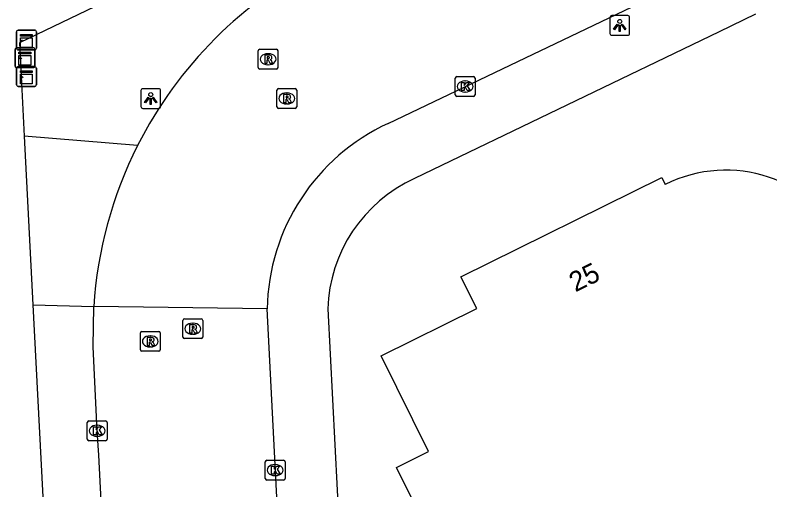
# Model space of a CAD drawing. Extents: x 157692 to 159670, y 381454 to 383289.
# Drawn here: x 158005 to 158043.16, y 381618.5 to 381642.51 of the extents above; entities that cross this region are included whole.
import ezdxf

# ---------------------------------------------------------------- set-up
doc = ezdxf.new("R2010")
doc.units = 0
for name, color, linetype in [('IMGEO_Kast', 7, 'Continuous'), ('IMGEO_Kolk', 7, 'Continuous'), ('IMGEO_Lichtpunt', 7, 'Continuous'), ('IMGEO_Pand', 7, 'Continuous'), ('IMGEO_Pand_nummerreeks', 7, 'Continuous'), ('IMGEO_Rijbaan_lokaal_gesloten', 7, 'Continuous'), ('IMGEO_Rioolput', 7, 'Continuous'), ('IMGEO_Voetpad_open', 7, 'Continuous')]:
    doc.layers.add(name, color=color, linetype=linetype)

msp = doc.modelspace()

# ---------------------------------------------------------------- linework, layer by layer
at = {"layer": 'IMGEO_Kast'}
for p, q in [((158005.076, 381640.825), (158005.076, 381641.666)), ((158005.076, 381641.666), (158005.076, 381640.825)), ((158005.151, 381641.75), (158005.992, 381641.75)), ((158005.992, 381641.75), (158005.151, 381641.75)), ((158006.076, 381641.675), (158006.076, 381640.834)), ((158006.076, 381640.834), (158006.076, 381641.675)), ((158005.001, 381639.931), (158005.001, 381640.772)), ((158005.001, 381640.772), (158005.001, 381639.931)), ((158005.076, 381640.856), (158005.917, 381640.856)), ((158005.917, 381640.856), (158005.076, 381640.856)), ((158006.001, 381640.75), (158005.16, 381640.75)), ((158005.16, 381640.75), (158006.001, 381640.75)), ((158006.001, 381640.781), (158006.001, 381639.94)), ((158006.001, 381639.94), (158006.001, 381640.781)), ((158005.075, 381638.983), (158005.075, 381639.824)), ((158005.075, 381639.824), (158005.075, 381638.983)), ((158005.926, 381639.856), (158005.085, 381639.856)), ((158005.085, 381639.856), (158005.926, 381639.856)), ((158005.15, 381639.908), (158005.991, 381639.908)), ((158005.991, 381639.908), (158005.15, 381639.908)), ((158006.075, 381639.833), (158006.075, 381638.992)), ((158006.075, 381638.992), (158006.075, 381639.833)), ((158006, 381638.908), (158005.159, 381638.908)), ((158005.159, 381638.908), (158006, 381638.908))]:
    msp.add_line(p, q, dxfattribs=at)
for points in [[(158005.271, 381641.54), (158005.871, 381641.54), (158005.871, 381641.455), (158005.271, 381641.455), (158005.271, 381641.54)], [(158005.271, 381641.365), (158005.871, 381641.365), (158005.871, 381640.876), (158005.271, 381640.876), (158005.271, 381641.365)], [(158005.196, 381640.646), (158005.796, 381640.646), (158005.796, 381640.561), (158005.196, 381640.561), (158005.196, 381640.646)], [(158005.196, 381640.471), (158005.796, 381640.471), (158005.796, 381639.982), (158005.196, 381639.982), (158005.196, 381640.471)], [(158005.27, 381639.698), (158005.87, 381639.698), (158005.87, 381639.613), (158005.27, 381639.613), (158005.27, 381639.698)], [(158005.27, 381639.523), (158005.87, 381639.523), (158005.87, 381639.034), (158005.27, 381639.034), (158005.27, 381639.523)]]:
    msp.add_lwpolyline(points, dxfattribs=at)
for centre in [(158005.355, 381641.214), (158005.28, 381640.32), (158005.354, 381639.372)]:
    msp.add_circle(centre, 0.0377, dxfattribs=at)
for centre, start, end in [((158005.154, 381641.672), 92.4484, 184.2845), ((158005.154, 381641.672), 92.4484, 184.2845), ((158005.998, 381641.672), 2.4484, 94.2845), ((158005.998, 381641.672), 2.4484, 94.2845), ((158005.079, 381640.778), 92.4484, 184.2845), ((158005.079, 381640.778), 92.4484, 184.2845), ((158005.154, 381640.828), 182.4484, 274.2845), ((158005.154, 381640.828), 182.4484, 274.2845), ((158005.923, 381640.778), 2.4484, 94.2845), ((158005.923, 381640.778), 2.4484, 94.2845), ((158005.998, 381640.828), 272.4484, 4.2845), ((158005.998, 381640.828), 272.4484, 4.2845), ((158005.079, 381639.934), 182.4484, 274.2845), ((158005.079, 381639.934), 182.4484, 274.2845), ((158005.153, 381639.83), 92.4484, 184.2845), ((158005.153, 381639.83), 92.4484, 184.2845), ((158005.923, 381639.934), 272.4484, 4.2845), ((158005.923, 381639.934), 272.4484, 4.2845), ((158005.997, 381639.83), 2.4484, 94.2845), ((158005.997, 381639.83), 2.4484, 94.2845), ((158005.153, 381638.986), 182.4484, 274.2845), ((158005.153, 381638.986), 182.4484, 274.2845), ((158005.997, 381638.986), 272.4484, 4.2845), ((158005.997, 381638.986), 272.4484, 4.2845)]:
    msp.add_arc(centre, 0.0779, start, end, dxfattribs=at)
at = {"layer": 'IMGEO_Kolk'}
for p, q in [((158027.33, 381639.402), (158028.182, 381639.402)), ((158027.255, 381638.476), (158027.255, 381639.328)), ((158027.743, 381639.182), (158027.768, 381639.182)), ((158028.256, 381639.328), (158028.256, 381638.476)), ((158027.766, 381638.622), (158027.741, 381638.622)), ((158028.182, 381638.402), (158027.33, 381638.402)), ((158008.652, 381621.062), (158008.652, 381621.914)), ((158008.727, 381621.988), (158009.579, 381621.988)), ((158009.653, 381621.914), (158009.653, 381621.062)), ((158009.14, 381621.768), (158009.165, 381621.768)), ((158009.163, 381621.208), (158009.138, 381621.208)), ((158009.579, 381620.988), (158008.727, 381620.988)), ((158017.651, 381619.073), (158017.651, 381619.925)), ((158017.726, 381619.999), (158018.578, 381619.999)), ((158018.652, 381619.925), (158018.652, 381619.073)), ((158018.139, 381619.779), (158018.164, 381619.779)), ((158018.162, 381619.219), (158018.137, 381619.219)), ((158018.578, 381618.999), (158017.726, 381618.999))]:
    msp.add_line(p, q, dxfattribs=at)
for points in [[(158027.33, 381639.402), (158028.182, 381639.402)], [(158027.255, 381638.476), (158027.255, 381639.328)], [(158027.576, 381639.102), (158027.699, 381639.102), (158027.699, 381638.951), (158027.829, 381639.102), (158027.993, 381639.102), (158027.847, 381638.951), (158028, 381638.702), (158027.848, 381638.702), (158027.763, 381638.866), (158027.699, 381638.799), (158027.699, 381638.702), (158027.576, 381638.702), (158027.576, 381639.102)], [(158028.256, 381639.328), (158028.256, 381638.476)], [(158028.182, 381638.402), (158027.33, 381638.402)], [(158008.652, 381621.062), (158008.652, 381621.914)], [(158008.727, 381621.988), (158009.579, 381621.988)], [(158009.653, 381621.914), (158009.653, 381621.062)], [(158008.973, 381621.688), (158009.096, 381621.688), (158009.096, 381621.537), (158009.226, 381621.688), (158009.39, 381621.688), (158009.244, 381621.537), (158009.397, 381621.288), (158009.245, 381621.288), (158009.16, 381621.452), (158009.096, 381621.385), (158009.096, 381621.288), (158008.973, 381621.288), (158008.973, 381621.688)], [(158009.579, 381620.988), (158008.727, 381620.988)], [(158017.651, 381619.073), (158017.651, 381619.925)], [(158017.726, 381619.999), (158018.578, 381619.999)], [(158018.652, 381619.925), (158018.652, 381619.073)], [(158017.972, 381619.699), (158018.095, 381619.699), (158018.095, 381619.548), (158018.225, 381619.699), (158018.389, 381619.699), (158018.243, 381619.548), (158018.396, 381619.299), (158018.244, 381619.299), (158018.159, 381619.463), (158018.095, 381619.396), (158018.095, 381619.299), (158017.972, 381619.299), (158017.972, 381619.699)], [(158018.578, 381618.999), (158017.726, 381618.999)]]:
    msp.add_lwpolyline(points, dxfattribs=at)
for centre, start, end in [((158027.332, 381639.326), 91.552, 178.448), ((158027.332, 381639.326), 91.552, 178.448), ((158028.18, 381639.326), 1.552, 88.448), ((158028.18, 381639.326), 1.552, 88.448), ((158027.332, 381638.478), 181.552, 268.448), ((158027.332, 381638.478), 181.552, 268.448), ((158028.18, 381638.478), 271.552, 358.448), ((158028.18, 381638.478), 271.552, 358.448), ((158008.729, 381621.912), 91.552, 178.448), ((158008.729, 381621.912), 91.552, 178.448), ((158009.577, 381621.912), 1.552, 88.448), ((158009.577, 381621.912), 1.552, 88.448), ((158008.729, 381621.064), 181.552, 268.448), ((158008.729, 381621.064), 181.552, 268.448), ((158009.577, 381621.064), 271.552, 358.448), ((158009.577, 381621.064), 271.552, 358.448), ((158017.728, 381619.923), 91.552, 178.448), ((158017.728, 381619.923), 91.552, 178.448), ((158018.576, 381619.923), 1.552, 88.448), ((158018.576, 381619.923), 1.552, 88.448), ((158017.728, 381619.075), 181.552, 268.448), ((158017.728, 381619.075), 181.552, 268.448), ((158018.576, 381619.075), 271.552, 358.448), ((158018.576, 381619.075), 271.552, 358.448)]:
    msp.add_arc(centre, 0.0765, start, end, dxfattribs=at)
for centre, major_axis, ratio, start_param, end_param in [((158027.742, 381638.902), (-0.387, 0.002), 0.722429, 4.712389, 7.853982), ((158027.767, 381638.902), (-0.39, 0.002), 0.717154, 1.570796, 4.712389), ((158009.139, 381621.488), (-0.387, 0.002), 0.722429, 4.712389, 7.853982), ((158009.164, 381621.488), (-0.39, 0.002), 0.717154, 1.570796, 4.712389), ((158018.138, 381619.499), (-0.387, 0.002), 0.722429, 4.712389, 7.853982), ((158018.163, 381619.499), (-0.39, 0.002), 0.717154, 1.570796, 4.712389)]:
    msp.add_ellipse(centre, major_axis=major_axis, ratio=ratio, start_param=start_param, end_param=end_param, dxfattribs=at)
at = {"layer": 'IMGEO_Lichtpunt'}
for p, q in [((158035.974, 381642.489), (158035.166, 381642.489)), ((158035.974, 381642.489), (158035.166, 381642.489)), ((158035.072, 381642.394), (158035.072, 381641.587)), ((158035.072, 381642.394), (158035.072, 381641.587)), ((158036.068, 381641.587), (158036.068, 381642.394)), ((158036.068, 381641.587), (158036.068, 381642.394)), ((158035.166, 381641.493), (158035.974, 381641.493)), ((158035.166, 381641.493), (158035.974, 381641.493)), ((158011.361, 381638.695), (158011.361, 381637.888)), ((158011.361, 381638.695), (158011.361, 381637.888)), ((158012.263, 381638.79), (158011.455, 381638.79)), ((158012.263, 381638.79), (158011.455, 381638.79)), ((158012.357, 381637.888), (158012.357, 381638.695)), ((158012.357, 381637.888), (158012.357, 381638.695)), ((158011.455, 381637.794), (158012.263, 381637.794)), ((158011.455, 381637.794), (158012.263, 381637.794))]:
    msp.add_line(p, q, dxfattribs=at)
for points in [[(158035.446, 381642.058), (158035.485, 381642.03), (158035.297, 381641.768), (158035.259, 381641.795), (158035.446, 381642.058)], [(158035.658, 381642.03), (158035.696, 381642.057), (158035.883, 381641.795), (158035.844, 381641.767), (158035.658, 381642.03)], [(158035.548, 381642.01), (158035.595, 381642.01), (158035.595, 381641.688), (158035.548, 381641.688), (158035.548, 381642.01)], [(158011.735, 381638.359), (158011.774, 381638.331), (158011.586, 381638.069), (158011.548, 381638.096), (158011.735, 381638.359)], [(158011.837, 381638.311), (158011.884, 381638.311), (158011.884, 381637.989), (158011.837, 381637.989), (158011.837, 381638.311)], [(158011.947, 381638.331), (158011.985, 381638.358), (158012.172, 381638.096), (158012.133, 381638.068), (158011.947, 381638.331)]]:
    msp.add_lwpolyline(points, dxfattribs=at)
for centre in [(158035.571, 381642.192), (158011.86, 381638.493)]:
    msp.add_circle(centre, 0.0994, dxfattribs=at)
for centre, start, end in [((158035.166, 381642.394), 90, 180), ((158035.166, 381642.394), 90, 180), ((158035.974, 381642.394), 0, 90), ((158035.974, 381642.394), 0, 90), ((158035.166, 381641.587), 180, 270), ((158035.166, 381641.587), 180, 270), ((158035.974, 381641.587), 270, 0), ((158035.974, 381641.587), 270, 360), ((158011.455, 381638.695), 90, 180), ((158011.455, 381638.695), 90, 180), ((158012.263, 381638.695), 0, 90), ((158012.263, 381638.695), 0, 90), ((158011.455, 381637.888), 180, 270), ((158011.455, 381637.888), 180, 270), ((158012.263, 381637.888), 270, 0), ((158012.263, 381637.888), 270, 360)]:
    msp.add_arc(centre, 0.0946, start, end, dxfattribs=at)
at = {"layer": 'IMGEO_Pand'}
msp.add_lwpolyline([(158028.252, 381603.508), (158025.855, 381608.353), (158027.466, 381609.152), (158025.068, 381613.997), (158026.68, 381614.795), (158024.283, 381619.64), (158025.895, 381620.438), (158023.502, 381625.274), (158028.337, 381627.668), (158027.54, 381629.28), (158037.689, 381634.301), (158037.867, 381633.943)], dxfattribs=at)
msp.add_arc((158040.936, 381627.824), 6.845, 26.6996, 116.6365, dxfattribs=at)
at = {"layer": 'IMGEO_Rijbaan_lokaal_gesloten'}
for points in [[(158023.865, 381637.038), (158039.259, 381644.417), (158041.132, 381645.32)], [(158009.936, 381607.028), (158009.812, 381609.052), (158009.233, 381620.257), (158009.154, 381621.489), (158008.948, 381625.733), (158008.979, 381627.772)], [(158017.739, 381627.652), (158008.979, 381627.772)], [(158019.039, 381603.737), (158018.776, 381607.631), (158018.733, 381608.273), (158017.739, 381627.652)]]:
    msp.add_lwpolyline(points, dxfattribs=at)
for centre, radius, start, end in [((158029.995, 381626.427), 21.061, 116.659, 153.2367), ((158028.309, 381627.445), 10.572, 114.8565, 178.8806), ((158029.925, 381626.449), 20.987, 153.2039, 176.3872)]:
    msp.add_arc(centre, radius, start, end, dxfattribs=at)
at = {"layer": 'IMGEO_Rioolput'}
for p, q in [((158017.291, 381639.857), (158017.291, 381640.709)), ((158017.366, 381640.783), (158018.218, 381640.783)), ((158017.779, 381640.563), (158017.804, 381640.563)), ((158018.292, 381640.709), (158018.292, 381639.857)), ((158018.218, 381639.783), (158017.366, 381639.783)), ((158017.802, 381640.003), (158017.777, 381640.003)), ((158018.237, 381637.871), (158018.237, 381638.723)), ((158018.312, 381638.797), (158019.164, 381638.797)), ((158019.238, 381638.723), (158019.238, 381637.871)), ((158018.725, 381638.577), (158018.75, 381638.577)), ((158018.748, 381638.017), (158018.723, 381638.017)), ((158019.164, 381637.797), (158018.312, 381637.797)), ((158013.56, 381627.149), (158014.412, 381627.149)), ((158013.485, 381626.223), (158013.485, 381627.075)), ((158013.973, 381626.929), (158013.998, 381626.929)), ((158014.486, 381627.075), (158014.486, 381626.223)), ((158011.334, 381625.584), (158011.334, 381626.436)), ((158011.409, 381626.51), (158012.261, 381626.51)), ((158012.335, 381626.436), (158012.335, 381625.584)), ((158011.822, 381626.29), (158011.847, 381626.29)), ((158014.412, 381626.149), (158013.56, 381626.149)), ((158013.996, 381626.369), (158013.971, 381626.369)), ((158011.845, 381625.73), (158011.82, 381625.73)), ((158012.261, 381625.51), (158011.409, 381625.51))]:
    msp.add_line(p, q, dxfattribs=at)
for points in [[(158017.291, 381639.857), (158017.291, 381640.709)], [(158017.366, 381640.783), (158018.218, 381640.783)], [(158018.292, 381640.709), (158018.292, 381639.857)], [(158017.88, 381640.481), (158017.628, 381640.483), (158017.628, 381640.083)], [(158017.628, 381640.083), (158017.752, 381640.083), (158017.752, 381640.245), (158017.763, 381640.245)], [(158017.806, 381640.402), (158017.752, 381640.402), (158017.752, 381640.321)], [(158017.752, 381640.321), (158017.804, 381640.321)], [(158017.81, 381640.216), (158017.881, 381640.083), (158018.021, 381640.083), (158017.956, 381640.209)], [(158018.218, 381639.783), (158017.366, 381639.783)], [(158018.237, 381637.871), (158018.237, 381638.723)], [(158018.312, 381638.797), (158019.164, 381638.797)], [(158019.238, 381638.723), (158019.238, 381637.871)], [(158018.826, 381638.495), (158018.574, 381638.497), (158018.574, 381638.097)], [(158018.574, 381638.097), (158018.698, 381638.097), (158018.698, 381638.259), (158018.709, 381638.259)], [(158018.752, 381638.416), (158018.698, 381638.416), (158018.698, 381638.335)], [(158018.698, 381638.335), (158018.75, 381638.335)], [(158018.756, 381638.23), (158018.827, 381638.097), (158018.967, 381638.097), (158018.902, 381638.223)], [(158019.164, 381637.797), (158018.312, 381637.797)], [(158013.56, 381627.149), (158014.412, 381627.149)], [(158013.485, 381626.223), (158013.485, 381627.075)], [(158014.074, 381626.847), (158013.822, 381626.849), (158013.822, 381626.449)], [(158014, 381626.768), (158013.946, 381626.768), (158013.946, 381626.687)], [(158014.486, 381627.075), (158014.486, 381626.223)], [(158011.334, 381625.584), (158011.334, 381626.436)], [(158011.409, 381626.51), (158012.261, 381626.51)], [(158012.335, 381626.436), (158012.335, 381625.584)], [(158013.822, 381626.449), (158013.946, 381626.449), (158013.946, 381626.611), (158013.957, 381626.611)], [(158013.946, 381626.687), (158013.998, 381626.687)], [(158014.004, 381626.582), (158014.075, 381626.449), (158014.215, 381626.449), (158014.15, 381626.575)], [(158011.923, 381626.208), (158011.671, 381626.21), (158011.671, 381625.81)], [(158011.849, 381626.129), (158011.795, 381626.129), (158011.795, 381626.048)], [(158011.795, 381626.048), (158011.847, 381626.048)], [(158014.412, 381626.149), (158013.56, 381626.149)], [(158011.671, 381625.81), (158011.795, 381625.81), (158011.795, 381625.972), (158011.806, 381625.972)], [(158011.853, 381625.943), (158011.924, 381625.81), (158012.064, 381625.81), (158011.999, 381625.936)], [(158012.261, 381625.51), (158011.409, 381625.51)]]:
    msp.add_lwpolyline(points, dxfattribs=at)
for centre, radius, start, end in [((158017.368, 381640.707), 0.0765, 91.552, 178.448), ((158017.368, 381640.707), 0.0765, 91.552, 178.448), ((158018.216, 381640.707), 0.0765, 1.552, 88.448), ((158018.216, 381640.707), 0.0765, 1.552, 88.448), ((158017.762, 381640.192), 0.0533, 26.0293, 88.6989), ((158017.788, 381640.51), 0.19, 274.7715, 282.9687), ((158017.812, 381640.306), 0.0964, 77.0061, 93.1865), ((158017.826, 381640.363), 0.0378, 276.6634, 79.6772), ((158017.879, 381640.371), 0.109, 350.3612, 89.416), ((158017.877, 381640.371), 0.112, 277.5842, 350.9817), ((158017.861, 381640.156), 0.108, 29.5134, 73.7905), ((158017.368, 381639.859), 0.0765, 181.552, 268.448), ((158017.368, 381639.859), 0.0765, 181.552, 268.448), ((158018.216, 381639.859), 0.0765, 271.552, 358.448), ((158018.216, 381639.859), 0.0765, 271.552, 358.448), ((158018.314, 381638.721), 0.0765, 91.552, 178.448), ((158018.314, 381638.721), 0.0765, 91.552, 178.448), ((158019.162, 381638.721), 0.0765, 1.552, 88.448), ((158019.162, 381638.721), 0.0765, 1.552, 88.448), ((158018.708, 381638.206), 0.0533, 26.0293, 88.6989), ((158018.734, 381638.524), 0.19, 274.7715, 282.9687), ((158018.758, 381638.32), 0.0964, 77.0061, 93.1865), ((158018.772, 381638.377), 0.0378, 276.6634, 79.6772), ((158018.825, 381638.385), 0.109, 350.3612, 89.416), ((158018.823, 381638.385), 0.112, 277.5842, 350.9817), ((158018.807, 381638.17), 0.108, 29.5134, 73.7905), ((158018.314, 381637.873), 0.0765, 181.552, 268.448), ((158018.314, 381637.873), 0.0765, 181.552, 268.448), ((158019.162, 381637.873), 0.0765, 271.552, 358.448), ((158019.162, 381637.873), 0.0765, 271.552, 358.448), ((158013.562, 381627.073), 0.0765, 91.552, 178.448), ((158013.562, 381627.073), 0.0765, 91.552, 178.448), ((158014.41, 381627.073), 0.0765, 1.552, 88.448), ((158014.41, 381627.073), 0.0765, 1.552, 88.448), ((158014.006, 381626.672), 0.0964, 77.0061, 93.1865), ((158014.02, 381626.729), 0.0378, 276.6634, 79.6772), ((158014.073, 381626.737), 0.109, 350.3612, 89.416), ((158011.411, 381626.434), 0.0765, 91.552, 178.448), ((158011.411, 381626.434), 0.0765, 91.552, 178.448), ((158012.259, 381626.434), 0.0765, 1.552, 88.448), ((158012.259, 381626.434), 0.0765, 1.552, 88.448), ((158013.956, 381626.558), 0.0533, 26.0293, 88.6989), ((158013.982, 381626.876), 0.19, 274.7715, 282.9687), ((158014.071, 381626.737), 0.112, 277.5842, 350.9817), ((158014.055, 381626.522), 0.108, 29.5134, 73.7905), ((158011.831, 381626.237), 0.19, 274.7715, 282.9687), ((158011.855, 381626.033), 0.0964, 77.0061, 93.1865), ((158011.869, 381626.09), 0.0378, 276.6634, 79.6772), ((158011.922, 381626.098), 0.109, 350.3612, 89.416), ((158011.92, 381626.098), 0.112, 277.5842, 350.9817), ((158013.562, 381626.225), 0.0765, 181.552, 268.448), ((158013.562, 381626.225), 0.0765, 181.552, 268.448), ((158014.41, 381626.225), 0.0765, 271.552, 358.448), ((158014.41, 381626.225), 0.0765, 271.552, 358.448), ((158011.805, 381625.919), 0.0533, 26.0293, 88.6989), ((158011.904, 381625.883), 0.108, 29.5134, 73.7905), ((158011.411, 381625.586), 0.0765, 181.552, 268.448), ((158011.411, 381625.586), 0.0765, 181.552, 268.448), ((158012.259, 381625.586), 0.0765, 271.552, 358.448), ((158012.259, 381625.586), 0.0765, 271.552, 358.448)]:
    msp.add_arc(centre, radius, start, end, dxfattribs=at)
for centre, major_axis, ratio, start_param, end_param in [((158017.778, 381640.283), (-0.387, 0.002), 0.722429, 4.712389, 7.853982), ((158017.803, 381640.283), (-0.39, 0.002), 0.717154, 1.570796, 4.712389), ((158018.724, 381638.297), (-0.387, 0.002), 0.722429, 4.712389, 7.853982), ((158018.749, 381638.297), (-0.39, 0.002), 0.717154, 1.570796, 4.712389), ((158013.972, 381626.649), (-0.387, 0.002), 0.722429, 4.712389, 7.853982), ((158013.997, 381626.649), (-0.39, 0.002), 0.717154, 1.570796, 4.712389), ((158011.821, 381626.01), (-0.387, 0.002), 0.722429, 4.712389, 7.853982), ((158011.846, 381626.01), (-0.39, 0.002), 0.717154, 1.570796, 4.712389)]:
    msp.add_ellipse(centre, major_axis=major_axis, ratio=ratio, start_param=start_param, end_param=end_param, dxfattribs=at)
at = {"layer": 'IMGEO_Voetpad_open'}
for points in [[(158032.78, 381654.365), (158005.223, 381641.106), (158005.466, 381636.382)], [(158042.438, 381642.559), (158040.595, 381641.674), (158025.192, 381634.25)], [(158011.191, 381635.911), (158005.466, 381636.382)], [(158005.466, 381636.382), (158005.905, 381627.867)], [(158005.905, 381627.867), (158008.979, 381627.772)], [(158005.905, 381627.867), (158006.881, 381609.083)], [(158020.806, 381627.665), (158021.984, 381604.726)]]:
    msp.add_lwpolyline(points, dxfattribs=at)
msp.add_arc((158028.334, 381627.404), 7.533, 114.6534, 178.0146, dxfattribs=at)

# ---------------------------------------------------------------- texts
at = {"layer": 'IMGEO_Pand_nummerreeks'}
msp.add_text('25', height=1, rotation=26.3229, dxfattribs=at).set_placement((158033.328, 381628.484))

doc.saveas('drawing.dxf')
